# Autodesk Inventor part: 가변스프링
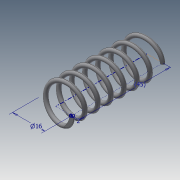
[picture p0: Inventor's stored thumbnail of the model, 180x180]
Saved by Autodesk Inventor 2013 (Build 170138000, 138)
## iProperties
Created: 2021-08
Part Number: 가변스프링
Material: Generic
Document SubType Name: Modeling
Designer: user
Density: 1 g/cm^3
Mass: 1.09305 g
Surface Area: 22.1036 cm^2
Volume: 1.09305 cm^3
Author: user
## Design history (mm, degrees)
sketch "스케치1"
  geometry: L1 (0, 0)-(8, 0); L2 (8, 0)-(8, 38); L3 (8, 38)-(0, 38); L4 (0, 38)-(0, 0); C1 r 1 at (8, 0)
  constraints: 8 end point, 2 parallel, 1 centre point, 1 coincident, 1 horizontal, 1 perpendicular
  dimensions: "d0" = 2 diameter of C1; "d1" = 38 distance of L1.end L2.end (derived); "d2" = 16 diameter of L2 L4
node "작업 평면1"
node "작업 평면2"
feature "코일2" pitch "d17" = 10; turns "d19" = 7; dims "d18" = 38 (= d1), "d20" = 0, angle "d21" = 90 deg, angle "d22" = 90 deg, "d23" = 0, "d24" = 0
node "작업 평면3"
sketch "스케치4"
  geometry: L1 (7, 0)-(9, 0) reference; 1 further point
  constraints: 1 horizontal alignment
extrude "돌출3" cut sketch "스케치4" distance "d26" = 10; taper "d27" = 0 deg
node "작업 평면4"
sketch "스케치5"
  geometry: L1 (-1, 0)-(1, 0) reference; 1 further point
  constraints: 1 horizontal alignment
extrude "돌출4" cut sketch "스케치5" distance "d29" = 10; taper "d30" = 0 deg
node "솔리드2"
node "절단 모서리 투영3"
node "절단 모서리 투영4"
other parameters: "d25" = 90 deg, "d28" = 90 deg
